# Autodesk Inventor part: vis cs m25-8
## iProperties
Author: chr
Created: 2002-03
Part Number: vis cs m25-8
Material: Par défaut
Document SubType Name: Modélisation
Designer: chr
Control State: 0
Master: False
Checked Out: False
PropertySet Name: Design Tracking Control
Shininess: 20.0
Angle Display Precision: 2
Document Length Units: 11269
Document Angle Units: 11283
Document Time Units: 11279
Document Mass Units: 11290
Document Length Units Precision: 3
Document Angle Units Precision: 2
Compacted: False
PropertySet Name: _Private Model Information
Density: 0.0
Volumn: 0.0
Area: 0.0
PropertySet Name: Model Information
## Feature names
1. Base1
